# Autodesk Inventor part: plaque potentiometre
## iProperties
Author: chr
Created: 2001-06
Part Number: plaque potentiometre
Material: Par défaut
Document SubType Name: Modélisation
Designer: chr
Control State: 0
Master: False
Checked Out: False
PropertySet Name: Design Tracking Control
Shininess: 20.0
PropertySet Name: _Private Model Information
Length Units: 11269
Angle Units: 11286
Time Units: 11279
Mass Units: 11290
Length Display Precision: 3
Angle Display Precision: 2
Compacted: False
Density: 0.0
Volumn: 0.0
Area: 0.0
PropertySet Name: Model Information
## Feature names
1. Extrusion1
2. Extrusion2
3. Extrusion3
4. Réseau rectangulaire1 [Rectangular Pattern]
5. Perçage1 [Hole]
